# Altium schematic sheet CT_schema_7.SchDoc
size 297 x 239 mm
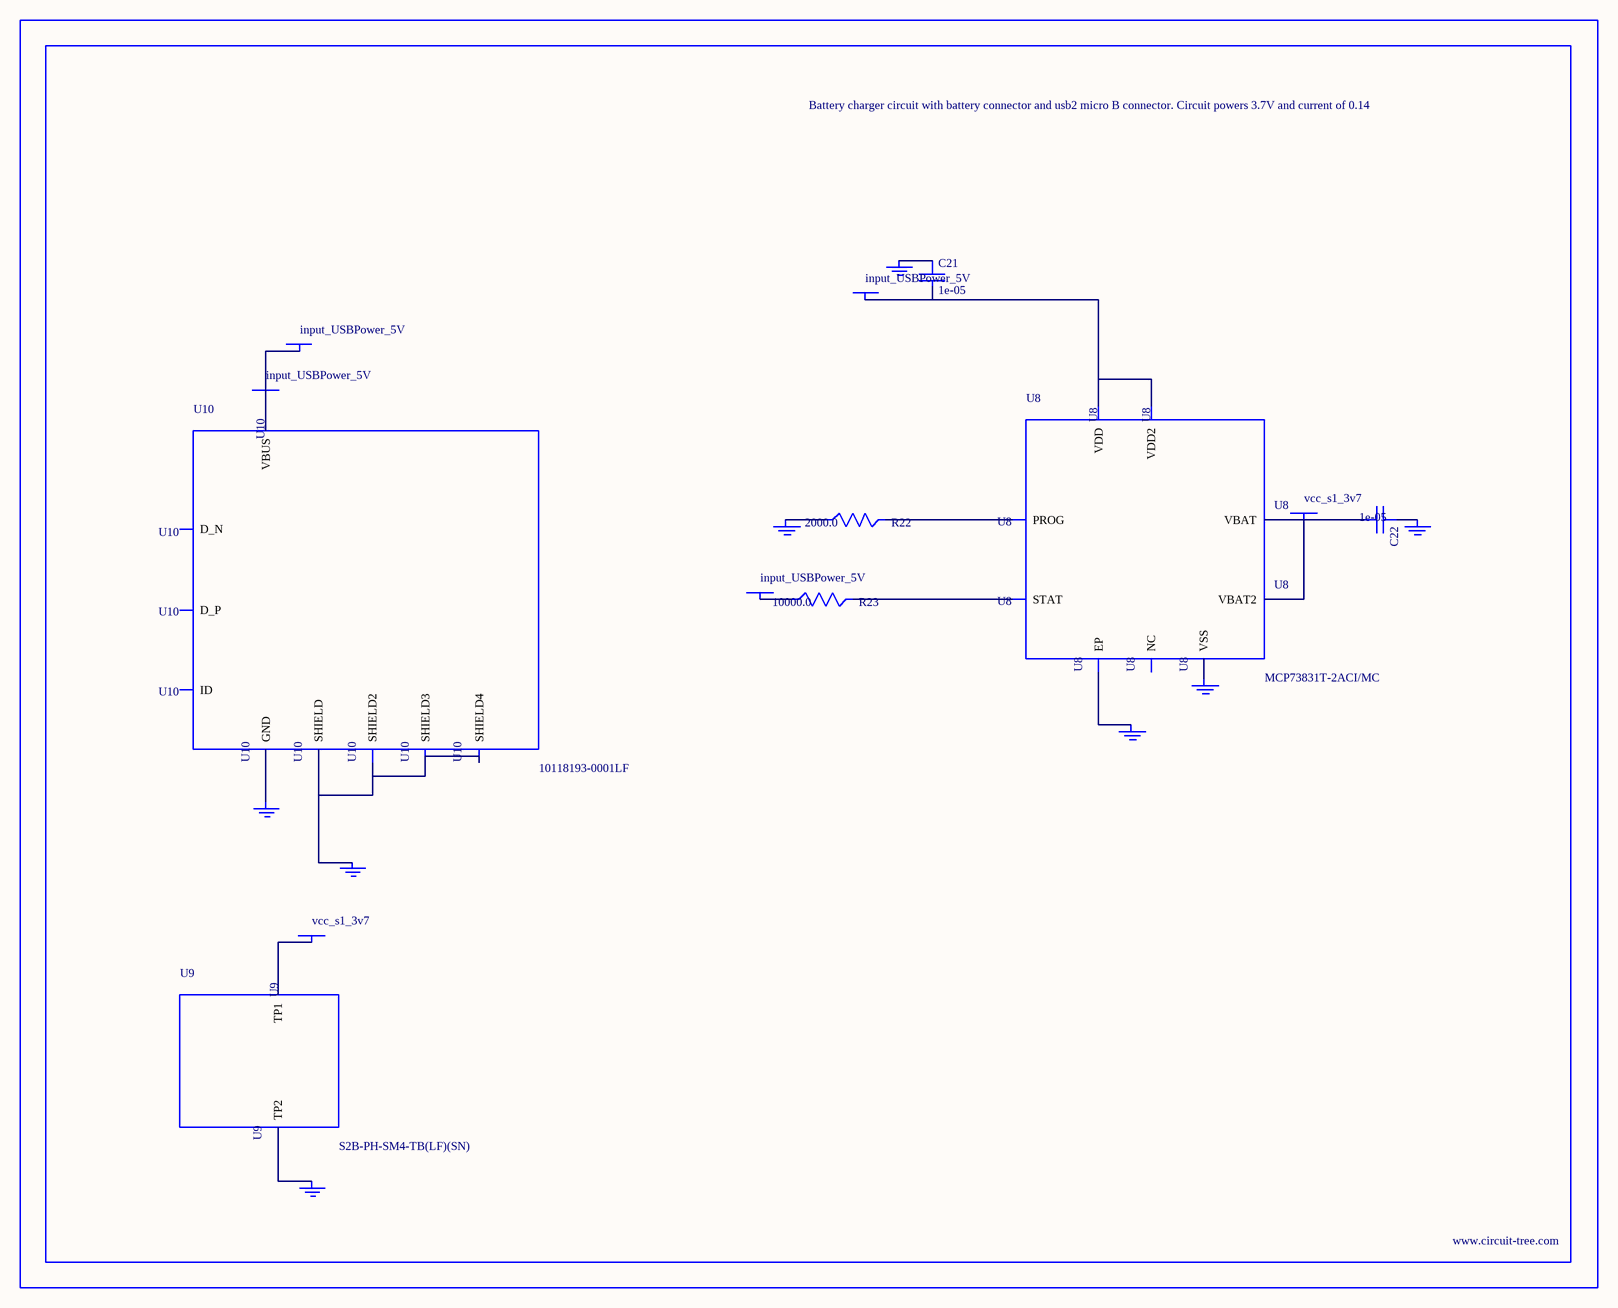
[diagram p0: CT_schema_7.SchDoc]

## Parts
BORDER6  (no value)
C21  1e-05  [C1206]
C22  1e-05  [C1206]
GND_INSTANCE_6_0  (no value)
GND_INSTANCE_6_1  (no value)
GND_INSTANCE_6_2  (no value)
GND_INSTANCE_6_3  (no value)
GND_INSTANCE_6_4  (no value)
GND_INSTANCE_6_5  (no value)
GND_INSTANCE_6_6  (no value)
GND_INSTANCE_6_7  (no value)
POWER_INSTANCE_6_0  input_USBPower_5V
POWER_INSTANCE_6_1  input_USBPower_5V
POWER_INSTANCE_6_2  vcc_s1_3v7
POWER_INSTANCE_6_3  vcc_s1_3v7
POWER_INSTANCE_6_4  input_USBPower_5V
POWER_INSTANCE_6_5  input_USBPower_5V
R22  2000.0  [R0603]
R23  10000.0  [R0603]
U8  MCP73831T-2ACI/MC  [DFN8_2X3MC]
U9  S2B-PH-SM4-TB(LF)(SN)  [JST-2-SMD]
U10  10118193-0001LF  [FCI_10118193-0001LF]

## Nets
NetC21_1: C21.1 GND_INSTANCE_6_0.0(GND)
NetC21_2: C21.2 POWER_INSTANCE_6_0.0(PWR) U8.1(VDD) U8.2(VDD2)
NetC22_1: C22.1 GND_INSTANCE_6_1.0(GND)
NetC22_2: C22.2 POWER_INSTANCE_6_2.0(PWR) U8.3(VBAT) U8.4(VBAT2)
NetGND_INSTANCE_6_2_0: GND_INSTANCE_6_2.0(GND) R22.1
NetGND_INSTANCE_6_3_0: GND_INSTANCE_6_3.0(GND) U8.9(EP)
NetGND_INSTANCE_6_4_0: GND_INSTANCE_6_4.0(GND) U8.6(VSS)
NetGND_INSTANCE_6_5_0: GND_INSTANCE_6_5.0(GND) U9.2(TP2)
NetGND_INSTANCE_6_6_0: GND_INSTANCE_6_6.0(GND) U10.6(SHIELD) U10.7(SHIELD2) U10.8(SHIELD3) U10.9(SHIELD4)
NetGND_INSTANCE_6_7_0: GND_INSTANCE_6_7.0(GND) U10.5(GND)
NetPOWER_INSTANCE_6_1_0: POWER_INSTANCE_6_1.0(PWR) R23.1
NetPOWER_INSTANCE_6_3_0: POWER_INSTANCE_6_3.0(PWR) U9.1(TP1)
NetPOWER_INSTANCE_6_4_0: POWER_INSTANCE_6_4.0(PWR) POWER_INSTANCE_6_5.0(PWR) U10.1(VBUS)
NetR22_2: R22.2 U8.8(PROG)
NetR23_2: R23.2 U8.5(STAT)

Not connected (* = marked no-connect by the designer): U8 7(NC); U10 2(D_N) 3(D_P) 4(ID)

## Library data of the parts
BORDER6 = BORDER_PAGE6
C21 C22 = C1206C106K3RACTU
GND_INSTANCE_6_0-GND_INSTANCE_6_7 = GND
POWER_INSTANCE_6_0-POWER_INSTANCE_6_5 = PWR
R22 = RC0603JR-072KL
R23 = RC0603JR-0710KL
